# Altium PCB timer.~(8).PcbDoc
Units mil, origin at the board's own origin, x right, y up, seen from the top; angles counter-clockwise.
Board outline 1968.5 x 1968.5 mil, 2 copper layers (Top Layer, Bottom Layer); 56 components, 43 nets, 162 pads, 42 vias.
Unrouted connection lines stored in the file: 53.
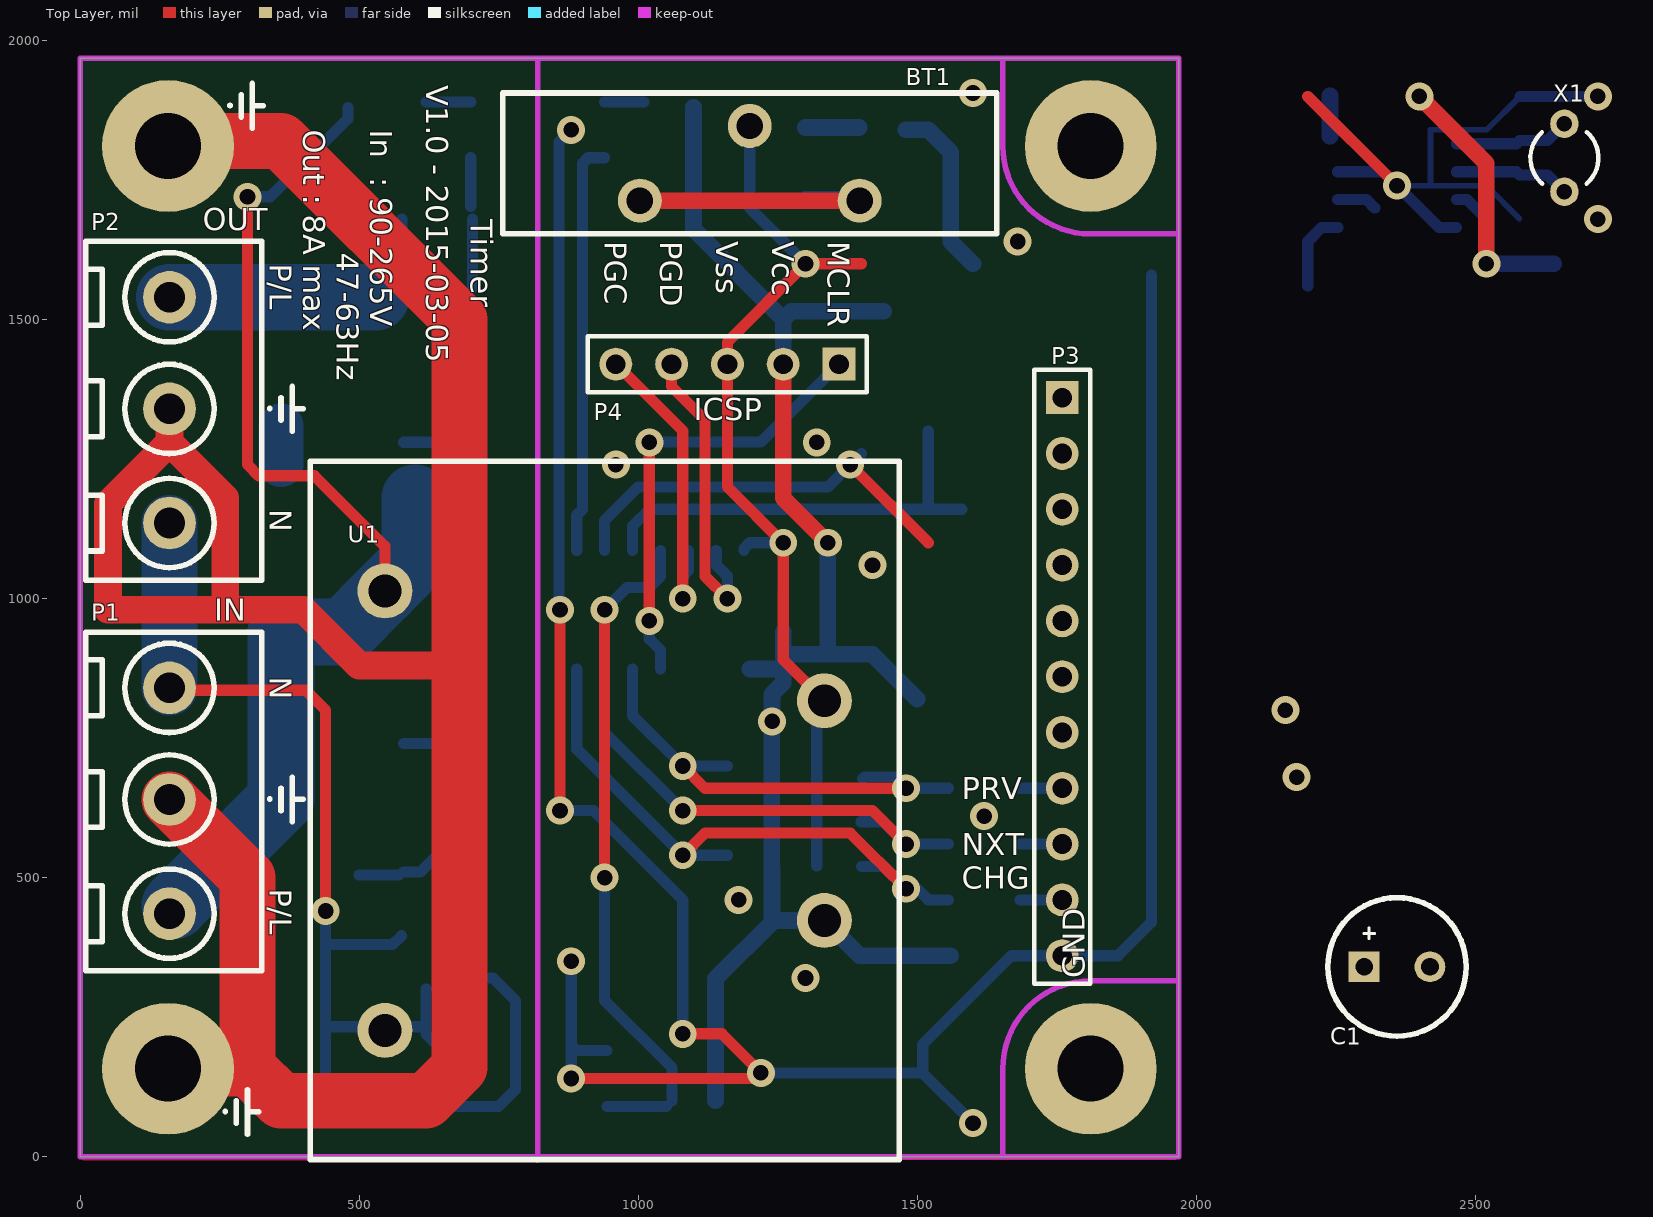
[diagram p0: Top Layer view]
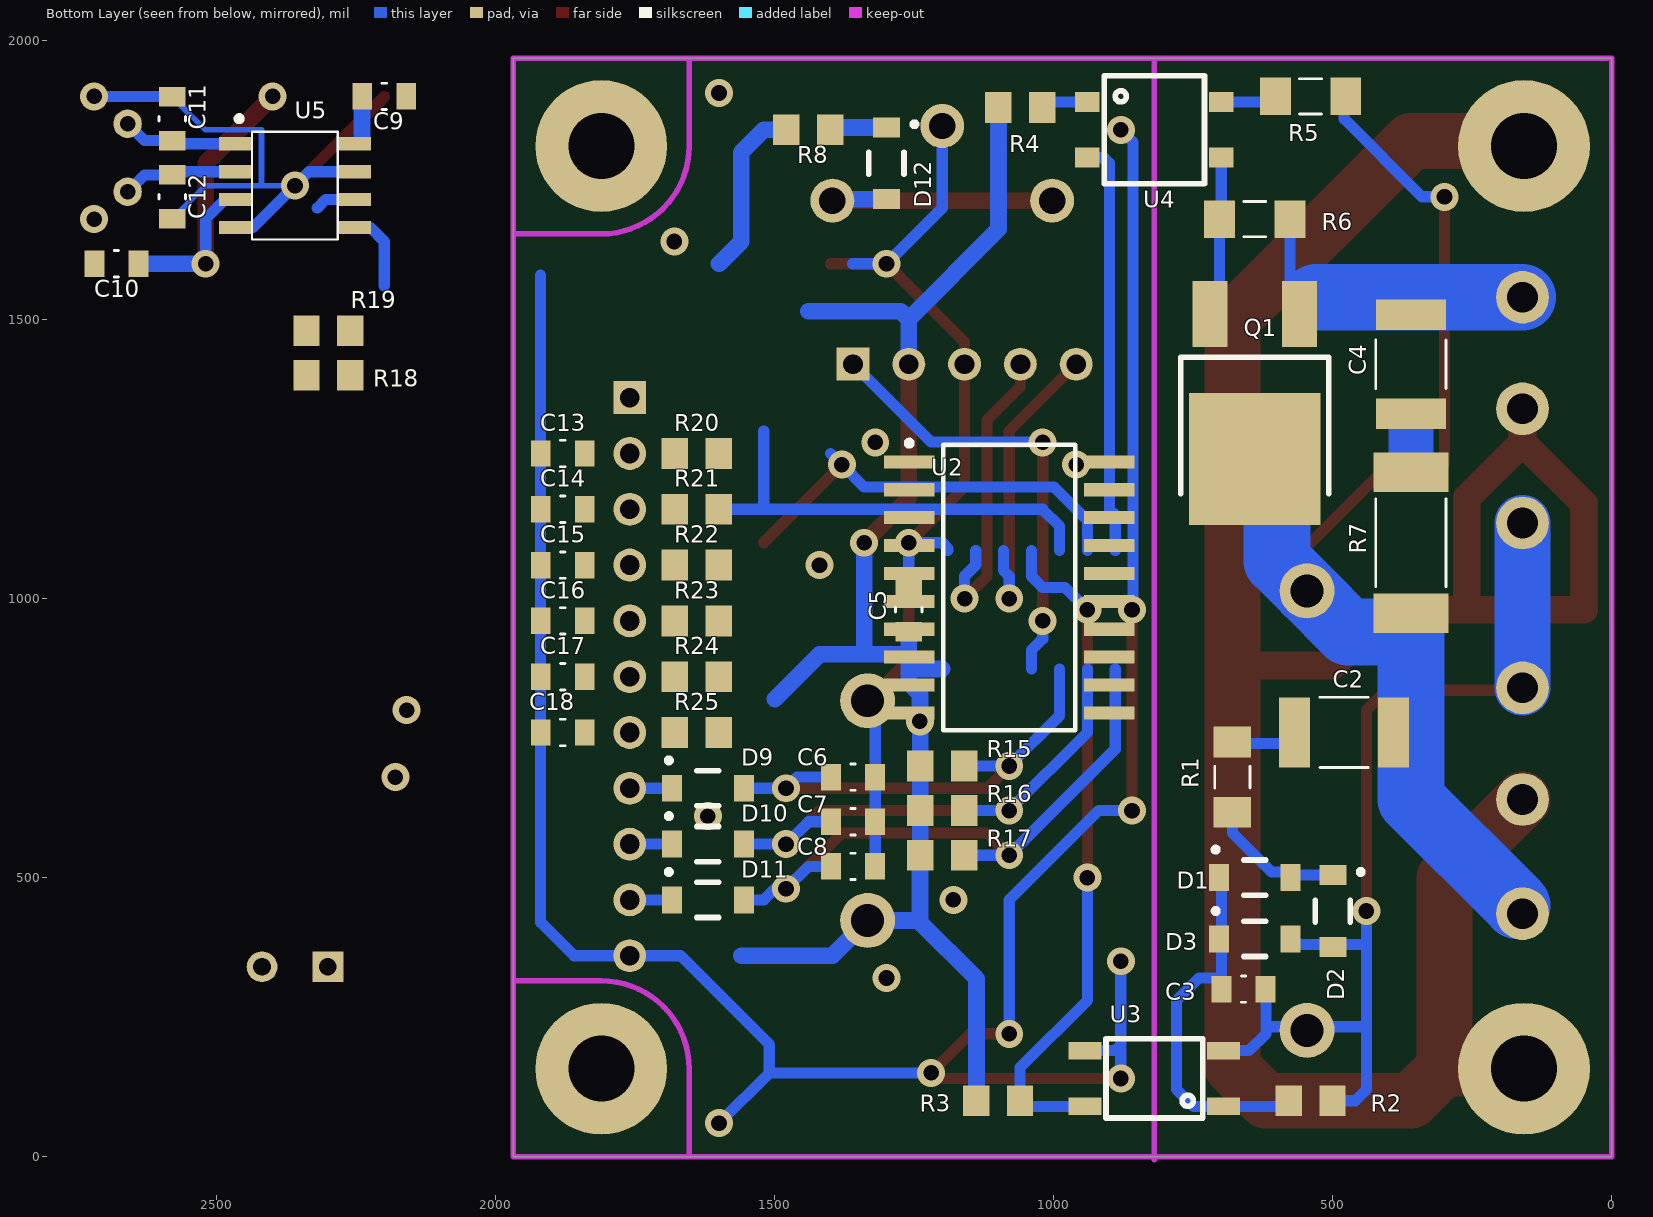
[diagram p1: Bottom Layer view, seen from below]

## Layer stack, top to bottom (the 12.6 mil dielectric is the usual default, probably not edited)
Top Layer: signal copper 1.4
Dielectric: core 12.6, FR-4, Dk 4.8
Bottom Layer: signal copper 1.4

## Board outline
0,0 1968.5,0 1968.5,1968.5 0,1968.5

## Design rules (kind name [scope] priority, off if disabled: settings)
Clearance RTC [InNetClass('RTC')] p1: gap=8
Clearance Earth [InNet('EARTH')] p2: gap=20
Clearance HT [InNetClass('HT') vs InNetClass('HT')] p3: gap=78.74
Clearance "plan masse" [All vs InNet('GND')] p4: gap=10
Clearance [All] p5: gap=20
HoleSize [All] p1: absolutevalues=TRUE maxlimit=196.85 minlimit=23.62 maxpercent=80.000 minpercent=20.000
PlaneConnect PlaneConnect_Via [isVia] p1: planeconnectstyle=Direct reliefexpansion=20 reliefentries=4 reliefconductorwidth=10 reliefairgap=10
PlaneConnect [All] p2: planeconnectstyle=Direct reliefexpansion=20 reliefentries=4 reliefconductorwidth=10 reliefairgap=10
PolygonConnect PolygonConnect_Via [IsVia] p1: connectstyle=Direct reliefconductorwidth=20 reliefentries=4 polygonreliefangle="90 Angle" airgapwidth=10
PolygonConnect [All] p2: connectstyle=Direct reliefconductorwidth=20 reliefentries=4 polygonreliefangle="90 Angle" airgapwidth=10
RoutingVias [All] p1: holewidth=39.37 width=78.74 viastyle="Through Hole" minholewidth=23.62 minwidth=31.5 maxholewidth=39.37 maxwidth=78.74
SilkToSolderMaskClearance SilkscreenOverComponentPads [IsPad] p1: minsilkscreentomaskgap=10 clearancetoexposedcopper=TRUE
SolderMaskExpansion [All] p1: expansion=4
Width overlay_width [(OnLayer('Top Overlay') OR OnLayer('Bottom Overlay'))] p1: maxlimit=10 minlimit=5 preferedwidth=10
Width [All] p2: maxlimit=150 minlimit=10 preferedwidth=20
25 further rules are at their usual default settings.

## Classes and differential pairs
net class RTC: NetC10_1 NetC11_1 NetC12_1
net class HT: N NetC4_1 NetC4_2 P

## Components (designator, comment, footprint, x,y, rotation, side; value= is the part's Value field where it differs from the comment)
BT1 "CR2032" BAT_2032 1200,1780 r0 top locked
C1 "470µ" CAP_6.3x2.5 2360,340 r0 top
C2 "10n 400V" C1812 480,760 r0 bottom
C3 "10n" C0805 660,300 r180 bottom
C4 "10n 400V" C1812 360,1420 r90 bottom
C5 "100n" C0805 1260,980 r270 bottom
C6 "100n" C0805 1360,680 r180 bottom
C7 "100n" C0805 1360,600 r180 bottom
C8 "100n" C0805 1360,520 r180 bottom
C9 "100n" C0805 2200,1900 r180 bottom
C10 "100p" C0805 2680,1600 r0 bottom
C11 "15p" C0805 2580,1860 r90 bottom
C12 "15p" C0805 2580,1720 r270 bottom
C13 "47p" C0805 1880,1260 r0 bottom
C14 "47p" C0805 1880,1160 r0 bottom
C15 "47p" C0805 1880,1060 r0 bottom
C16 "47p" C0805 1880,960 r0 bottom
C17 "47p" C0805 1880,860 r0 bottom
C18 "47p" C0805 1880,760 r0 bottom
D1 "MBR0520LT" SOD-123 640,500 r0 bottom
D2 "MBR0520LT" SOD-123 500,440 r90 bottom
D3 "5V1" SOD-123 640,390 r0 bottom
D9 "MBR0520LT" SOD-123 1620,660 r0 bottom
D10 "MBR0520LT" SOD-123 1620,560 r0 bottom
D11 "MBR0520LT" SOD-123 1620,460 r0 bottom
D12 "MBR0520LT" SOD-123 1300,1780 r90 bottom
P1 "5.08x3" "BORNIER 5.08X3" 160,640 r270 top locked
P2 "5.08x3" "BORNIER 5.08X3" 160,1340 r270 top locked
P3 "2.54x11" HDR1X11 1760,1360 r270 top
P4 "2.54x5" HDR1X5 1360,1420 r180 top locked
Q1 "BT137S-600D" DPAK 640,1310 r0 bottom
R1 "10k" R1206 680,680 r90 bottom
R2 "100k" R0805 540,100 r180 bottom
R3 "10k" R0805 1100,100 r0 bottom
R4 "1k" R0805 1060,1880 r0 bottom
R5 "56" R1206 540,1900 r0 bottom
R6 "330" R1206 640,1680 r0 bottom
R7 "100 1W" R2512 360,1100 r90 bottom
R8 "1k" R0805 1440,1840 r0 bottom
R15 "10k" R0805 1200,700 r0 bottom
R16 "10k" R0805 1200,620 r0 bottom
R17 "10k" R0805 1200,540 r0 bottom
R18 "2k2" R0805 2300,1400 r180 bottom
R19 "2k2" R0805 2300,1480 r0 bottom
R20 "1k" R0805 1640,1260 r0 bottom
R21 "1k" R0805 1640,1160 r0 bottom
R22 "1k" R0805 1640,1060 r0 bottom
R23 "1k" R0805 1640,960 r0 bottom
R24 "1k" R0805 1640,860 r0 bottom
R25 "1k" R0805 1640,760 r0 bottom
U1 "AC-DC 5V 600mA" "AC-DC 3W" 940,620 r0 top locked
U2 "PIC16F1825" SOIC-20 1080,1020 r180 bottom
U3 "PC357N14J00F" OPTO_PC357N14J00F 820,140 r0 bottom
U4 "VOM160RT" OPTO_VOM160RT 820,1840 r180 bottom
U5 "MCP7940N" SOIC-8 2360,1740 r180 bottom
X1 "32.768kHz" R38 2660,1790 r0 top

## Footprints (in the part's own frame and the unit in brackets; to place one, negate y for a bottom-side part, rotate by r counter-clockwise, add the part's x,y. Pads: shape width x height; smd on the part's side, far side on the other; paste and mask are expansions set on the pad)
"AC-DC 3W" [mm]
  round 2.5 hole 1.5: 1(-10,10) 2(-10,-10) 3(10,-5) 4(10,5)
  silkscreen extent -13.4,-15.9 13.4,15.9, body extent -13.4,-15.9 13.4,15.9, height 19.5
BAT_2032 [mm] "Battery holder 2032"
  round 2 hole 1.2: +(-5,-1.7) +(5,-1.7) -(0,1.7)
  silkscreen extent -11.25,-3.2 11.25,3.2, body extent -11.25,-3.2 11.25,3.2, height 25
"BORNIER 5.08X3" [mm] "Bornier 5.08x3"
  round 2.4 hole 1.4: 1(-5.08,0) 2(0,0) 3(5.2,0)
  silkscreen extent -7.62,-3.8 7.8,4.2
C0805 [mm]
  rect 0.9x1.2 smd: 1(-1,0) 2(1,0)
  silkscreen extent -0.1,-0.6 0.1,0.6, body extent -1,-0.6 1,0.6, height 1.2
C1812 [mm]
  rect 1.4x3.2 smd: 1(-2.25,0) 2(2.25,0)
  silkscreen extent -1.1,-1.6 1.1,1.6, body extent -2.25,-1.6 2.25,1.6, height 3.2
CAP_6.3x2.5 [mm] "Capacitor throug hole dia=6.3mm, H=11mm, spacing=2.5mm"
  rect 1.4x1.4 hole 0.8: 1(-1.5,0)
  round 1.4 hole 0.8: 2(1.5,0)
  silkscreen extent -3.15,-3.15 3.15,3.15, body extent -3.12,-3.14 3.15,3.14, height 11
DPAK [mm] "DPAK"
  rect 1.6x3 smd: 1(-2.032,-5.08) 3(2.032,-5.08)
  rect 6x6 smd: 2(0,1.524)
  silkscreen extent -3.36,-3.11 3.36,3.11, body extent -3.36,-3.11 3.36,3.11, height 2.38
HDR1X5 [mm] "Connector; Header; 5 Position"
  rect 1.5x1.5 hole 0.9: 1(0,0)
  round 1.5 hole 0.9: 2(2.54,0) 3(5.08,0) 4(7.62,0) 5(10.16,0)
  silkscreen extent -1.27,-1.27 11.43,1.27
HDR1X11 [mm] "Connector; Header; 11 Position"
  rect 1.5x1.5 hole 0.9: 1(0,0)
  round 1.5 hole 0.9: 2(2.54,0) 3(5.08,0) 4(7.62,0) 5(10.16,0) 6(12.7,0) 7(15.24,0) 8(17.78,0) 9(20.32,0) 10(22.86,0) 11(25.4,0)
  silkscreen extent -1.27,-1.27 26.67,1.27
OPTO_PC357N14J00F [mm] "optocoupleur"
  rect 1.5x0.8 smd: 1(-3.15,1.27) 2(-3.15,-1.27) 3(3.15,-1.27) 4(3.15,1.27)
  silkscreen extent -2.2,-1.8 2.2,1.8, body extent -2.2,-1.8 2.2,1.8, height 2.6
OPTO_VOM160RT [mm] "Opto-triac"
  rect 1.11x0.91 smd: 1(-3.048,1.27) 2(-3.048,-1.27) 3(3.048,-1.27) 4(3.048,1.27)
  silkscreen extent -2.28,-2.46 2.28,2.46, body extent -2.28,-2.46 2.28,2.46, height 1.97
R38 [mm] "Crystal, Thru-Hole; 2 Leads; Body 3.1 x 8.2 mm (Dia.xH)"
  round 1.3 hole 0.7: 1(0,1.55) 2(0,-1.55)
  silkscreen extent -1.55,-1.19 1.55,1.17
R0805 [mm] "0.125W"
  rect 1.2x1.4 smd: 1(-1,0) 2(1,0)
  body extent -1,-0.63 1,0.63, height 1.2
R1206 [mm] "0.25W"
  rect 1.4x1.7 smd: 1(-1.6,0) 2(1.6,0)
  silkscreen extent -0.5,-0.8 0.5,0.8, body extent -1.6,-0.8 1.6,0.8, height 1.6
R2512 [mm] "1W"
  rect 1.8x3.4 smd: 1(-3.2,0) 2(3.2,0)
  silkscreen extent -2,-1.6 2,1.6, body extent -3.2,-1.6 3.2,1.6, height 5
SOD-123 [mm] "Diode"
  rect 0.91x1.22 smd: 1(-1.635,0) 2(1.635,0)
  silkscreen extent -0.5,-1.37 1.88,0.8, body extent -1.35,-0.8 1.35,0.8, height 1.17
SOIC-8 [mm] "8-Pin Plastic Narrow Body Small Outline Integrated Circuit 1.27 mm Pitch, IPC Medium Density"
  rect 1.5x0.6 smd: 1(-2.7,1.905) 2(-2.7,0.635) 3(-2.7,-0.635) 4(-2.7,-1.905) 5(2.7,-1.905) 6(2.7,-0.635) 7(2.7,0.635) 8(2.7,1.905)
  silkscreen extent -2.67,-2.45 1.95,3.17, body extent -1.95,-2.45 1.95,2.45, height 1.76
SOIC-20 [mm] "20-Pin Plastic Wide Body Small Outline Integrated Circuit 1.27 mm Pitch, IPC Medium Density"
  rect 2.3x0.6 smd: 1(-4.55,5.715) 2(-4.55,4.445) 3(-4.55,3.175) 4(-4.55,1.905) 5(-4.55,0.635) 6(-4.55,-0.635) 7(-4.55,-1.905) 8(-4.55,-3.175) 9(-4.55,-4.445) 10(-4.55,-5.715) 11(4.55,-5.715) 12(4.55,-4.445) 13(4.55,-3.175) 14(4.55,-1.905) 15(4.55,-0.635) 16(4.55,0.635) 17(4.55,1.905) 18(4.55,3.175) 19(4.55,4.445) 20(4.55,5.715)
  silkscreen extent -4.67,-6.5 3,6.69, body extent -3.75,-6.4 3.75,6.4, height 2.65

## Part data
BT1: library part Battery, "Multicell Battery"
C1: library part "Cap Pol1", "Polarized Capacitor (Radial)"
C2 C3 C4 C5 C6 C7 C8 C9 C10 C11 C12 C13 C14 C15 C16 C17 C18: library part Cap, "Capacitor"
D1 D2 D9 D10 D11 D12: library part "Diode 1N4001", "1 Amp General Purpose Rectifier"
D3: library part "D Zener", "Zener Diode"
P1 P2: library part "Header 3", "Header, 3-Pin"
P3: library part "Header 11", "Header, 11-Pin"
P4: library part "Header 5", "Header, 5-Pin"
Q1: library part Triac, "Silicon Bidirectional Triode Thyristor"
R1 R2 R3 R4 R5 R6 R7 R8 R15 R16 R17 R18 R19 R20 R21 R22 R23 R24 R25: library part Res2, "Resistor"
U1: library part AC-DC
U2: library part PIC16F1829
U3: library part Optoisolator1, "4-Pin Phototransistor Optocoupler"
U4: library part "Opto TRIAC", "Opto-Triac"
U5: library part "RTC- MCP7940N"
X1: library part XTAL, "Crystal Oscillator"

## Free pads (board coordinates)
  round 236.22 hole 118.11: 0(157.48,157.48) 0(157.48,1811.02) 0(1811.02,157.48) 0(1811.02,1811.02)

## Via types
v1: diameter 50, hole 28, Top Layer to Bottom Layer, 42 vias

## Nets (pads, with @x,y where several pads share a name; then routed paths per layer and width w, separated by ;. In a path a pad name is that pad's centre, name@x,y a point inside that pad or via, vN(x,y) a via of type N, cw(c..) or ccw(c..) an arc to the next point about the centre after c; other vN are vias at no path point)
BP_CHG: C8.1 D11.1 R17.1 U2.12 | length 1187.4
  Top Layer w20: v1(1080,540) 1120,580 1380,580 v1(1480,480) 1440,520
  Bottom Layer w20: 890,873.7 890,730 v1(1080,540) R17.1@1160,540 ; C8.1@1400,520 1440,520 v1(1480,480) 1500,480 1520,460 D11.1
BP_NXT: C7.1 D10.1 R16.1 U2.2 | length 989.4
  Top Layer w20: v1(1080,620) 1420,620 v1(1480,560)
  Bottom Layer w20: 940,873.7 940,760 v1(1080,620) R16.1@1160,620 ; C7.1 1440,600 v1(1480,560) D10.1
BP_PRV: C6.1 D9.1 R15.1 U2.3 | length 870.3
  Top Layer w20: v1(1080,700) 1120,660 v1(1480,660)
  Bottom Layer w20: 990,873.7 990,790 v1(1080,700) R15.1@1160,700 ; C6.1@1402.38,676.99 1405.39,680 1460,680 v1(1480,660) D9.1
EARTH: P1.2 P2.2 pad.0@157.48,157.48 pad.0@157.48,1811.02 | length 4671.4
  Top Layer w50: P2.2 160,1280 ; 680,880 500,880 400,980 260,980 ; 160,1280 50,1170 50,980 260,980 ; 160,1280 260,1180 260,980
  Top Layer w100: pad.0@157.48,1811.02 166.46,1820 360,1820 680,1500 680,880 680,160 620,100 360,100 302.52,157.48 157.48,157.48 300,157.48 300,500 P1.2
GND: BT1.- C1.2 C5.1 C6.2 C7.2 C8.2 C9.2 C10.2 C11.2 C12.2 C13.2 C14.2 C15.2 C16.2 C17.2 C18.2 P3.11 P4.3 U1.4 U2.20 U3.3 U5.4 U5.7 | length 7654.4
  Top Layer w20: v1(860,620) v1(860,980) ; v1(880,140) v1@1210,140 ; v1(1080,220) 1150,220 v1(1220,150) ; U1.4 1260,890.55 v1(1260,1100) 1160,1200 P4.3 1160,1460 v1(1300,1600) 1400,1600 ; 2200,1900 v1(2360,1740)
  Bottom Layer w10: v1(2360,1740) 2420,1740 ; C12.2@2579.37,1680.63 2520,1740 2420,1740 ; C11.2 2520.63,1840 2420,1840 2420,1740
  Bottom Layer w20: v1(860,620) 920,620 1080,460 1080,230 v1@1070,220 ; v1(860,980) 858.19,981.81 858.19,1818.19 v1(880,1840) ; v1(880,140) 880,200 ; v1(880,350) 880,200 ; U3.3 890,190 880,200 ; 1190,1086.3 1190,1090 1200,1100 v1(1260,1100) C5.1 ; BT1.- 1200,1700 v1(1300,1600) 1360.63,1600 ; v1(1220,150) 1510,150 ; C8.2@1320,520.63 U1.4@1320,840 ; v1(1600,60) 1510,150 ; 1920,1580 1920,420 1860,360 1669.06,360 1510,200.94 1510,150 ; U5.7 2335,1765 v1(2360,1740) 2435,1665 U5.4 ; C11.2@2580.63,1900 v1(2720,1900)
  other v1: 1300,320 1180,460 1620,610 2180,680 2160,800 1420,1060 960,1240 1320,1280 1680,1640 2720,1680 1600,1905.98
LCD_D4: R22.1 U2.7
LCD_D5: R23.1 U2.8
LCD_D6: R24.1 U2.9
LCD_D7: R25.1 U2.10
LCD_E: R21.1 U2.6
LCD_RS: R20.1 U2.5
MCLR: P4.1 U2.4 | length 812.4
  Top Layer w20: v1(1020,960) v1(1020,1280)
  Bottom Layer w20: v1(1020,960) 1020,927.47 1040,907.47 1040,873.7 ; v1@1020,1280.39 1220.39,1280.39 P4.1
N: C3.2 D2.1 D3.1 P1.1 P2.3 R2.2 U1.2 U3.2 | length 1834.8
  Top Layer w20: P1.1@164.25,835.75 404.25,835.75 440,800 v1(440,440)
  Bottom Layer w20: 440,380 560,380 D3.1@575.63,395.63 ; v1(440,440) 440,232.6 ; R2.2 460,100 440,120 440,232.6 ; 620,232.6 540,232.6 440,232.6 ; C3.2 620,300 620,220 650,190 U3.2
  Bottom Layer w50: U1.2@540,232.6 U1.2
  Bottom Layer w100: P1.1 P2.3
NetBT1_1: BT1.+ D12.1 | length 488
  Top Layer w30: BT1.+@1003.15,1713.07 BT1.+@1396.85,1713.07
  Bottom Layer w30: D12.1 BT1.+@1394.29,1715.63
NetC2_2: C2.2 R1.2 | length 100
  Bottom Layer w20: C2.2@580,740 R1.2@680,740
NetC3_1: C3.1 D1.2 D3.2 R2.1 U3.1 | length 639.6
  Bottom Layer w20: R2.1@580,90 U3.1 750,90 780,120 780,280 740,320 699.37,320 D1.2@699.37,490
NetC4_1: C4.1 R7.2 | length 70
  Bottom Layer w80: R7.2@360,1240 C4.1@360,1310
NetC4_2: C4.2 P2.1 Q1.1 R6.1 | length 523
  Bottom Layer w20: Q1.1@577.01,1527.01 R6.1
  Bottom Layer w120: P2.1 Q1.1@530,1540
NetC10_1: C10.1 R8.2 U5.3 | length 932.3
  Top Layer w30: v1(2400,1900) 2520,1780 v1(2520,1600)
  Bottom Layer w20: U5.3 2485,1715 2520,1680 v1(2520,1600)
  Bottom Layer w30: R8.2 1520,1840 1560,1800 1560,1640 1600,1600 ; v1(2520,1600) C10.1
NetC11_1: C11.1 U5.1 X1.1 | length 200.7
  Bottom Layer w20: U5.1 C11.1@2574.37,1815 ; C11.1 2629.61,1820.63 X1.1
NetC12_1: C12.1 U5.2 X1.2 | length 200.7
  Bottom Layer w20: U5.2 C12.1@2574.37,1765 ; C12.1 2629.61,1759.37 X1.2
NetD1_1: D1.1 D2.2 R1.1 | length 220.3
  Bottom Layer w20: D2.2 D1.1@571.26,504.37 ; D1.1@580,510 610,510 680,580 R1.1@680,600
NetD12_2: D12.2 R8.1 | length 96.3
  Bottom Layer w30: D12.2 R8.1@1396.26,1844.37
NetQ1_3: Q1.3 R6.2 U4.3 | length 210
  Bottom Layer w20: R6.2@700,1702.99 U4.3 ; Q1.3@702.99,1557.01 R6.2
NetR4_1: R4.1 U4.1 | length 70
  Bottom Layer w20: U4.1 R4.1@1010,1890
NetR5_2: R5.2 U4.4 | length 80
  Bottom Layer w20: R5.2@620,1890 U4.4
P: C2.1 P1.3 Q1.2 R5.1 R7.1 U1.1 | length 2179
  Top Layer w20: v1(300,1720) 300,1240 320,1220 420,1220 546.3,1093.7 U1.1
  Bottom Layer w20: v1(300,1720) 340,1720 480,1860 R5.1@480,1880 ; Q1.2@580,1280 Q1.2@660,1280
  Bottom Layer w120: P1.3@170,450 360,640 360,940 472.6,940 U1.1 600,1067.4 Q1.2@600,1180
P_BP_CHG: D11.2 P3.10 | length 75.6
  Bottom Layer w20: D11.2 P3.10
P_BP_NXT: D10.2 P3.9 | length 75.6
  Bottom Layer w20: D10.2 P3.9
P_BP_PRV: D9.2 P3.8 | length 75.6
  Bottom Layer w20: D9.2 P3.8
P_LCD_D4: C15.1 P3.4 R22.2
P_LCD_D5: C16.1 P3.5 R23.2
P_LCD_D6: C17.1 P3.6 R24.2
P_LCD_D7: C18.1 P3.7 R25.2
P_LCD_E: C14.1 P3.3 R21.2
P_LCD_RS: C13.1 P3.2 R20.2
PGC: P4.5 U2.18 | length 560.1
  Top Layer w20: P4.5 1080,1300 v1(1080,1000)
  Bottom Layer w20: v1(1080,1000) 1080,1040 1090,1050 1090,1086.3
PGD: P4.4 U2.19 | length 556
  Top Layer w20: P4.4 1060,1380 1120,1320 1120,1040 v1(1160,1000)
  Bottom Layer w20: 1140,1086.3 1140,1060 1160,1040 v1(1160,1000)
POWER: U2.14 U4.2 | length 742
  Bottom Layer w20: 890,1086.3 890,1150 900,1160 900,1780 910,1790 U4.2
SCL: R18.2 U2.11 U5.6 | length 858.6
  Bottom Layer w20: 990,1086.3 990,1130 1020,1160 1520,1160 ; 1520,1300 1520,1160 ; 1580,1160 1520,1160 ; U5.6 2305,1715 2320,1700
SDA: R19.2 U2.13 U5.5 | length 905.5
  Top Layer w20: v1(1380,1240) 1520,1100
  Bottom Layer w20: 940,1086.3 940,1140 1000,1200 1340,1200 v1(1380,1240) 1400,1260 ; 2200,1560 2200,1640 2225,1665 U5.5
SIGNAL: R3.1 U2.17 U3.4 | length 1207.7
  Top Layer w20: v1(940,500) v1(940,980)
  Bottom Layer w20: v1(940,500) 940,280 1060.63,159.37 R3.1 ; v1(940,980) 980,1020 1020,1020 1040,1040 1040,1086.3 ; U3.4 R3.1@1050.63,90
VCC: C1.1 C5.2 C9.1 P3.1 P4.2 R3.2 R4.2 R15.2 R16.2 R17.2 R18.1 R19.1 U1.3 U2.1 U5.8 | length 2894
  Top Layer w30: P4.2 1260,1180 v1(1340,1100)
  Bottom Layer w30: R4.2 1099.37,1661.89 1260,1501.26 1260,1500 ; R3.2@1138.74,100 1138.74,318.74 1243.15,423.15 U1.3 ; 1200,873.7 1253.7,873.7 ; v1@1239.37,780 R15.2 R16.2 1240,423.15 ; v1(1240,780) 1240,828.61 1260,848.61 1260,900 ; C5.2 1260,900 ; P4.2 1260,1500 ; U1.3@1337.8,419.06 1396.85,360 1560,360 ; v1(1340,1100) 1340,900 ; 1440,1515 1275,1515 1260,1500 ; 1500,820 1420,900 1340,900 ; 2240,1828.7 C9.1@2240,1900.63 ; 1260,900 1340,900
pads on no net: U2.15 U2.16

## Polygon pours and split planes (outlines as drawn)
EARTH on Top Layer "Earth-Top" (solid, shelved, pour order 3): 0,0 5.98,-5.98 820,-5.98 820,1968.5 0,1968.5
GND on Top Layer "GND-Top" (solid, remove dead copper, shelved, pour order 7): 1968.5,0 1962.52,-5.98 820,-5.98 820,1968.5 1968.5,1968.5
GND on Bottom Layer "GND-Bottom" (solid, remove dead copper, shelved, pour order 5): 1968.5,0 820,0 820,1968.5 1968.5,1968.5

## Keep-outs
Top Layer:
  lines w10: 820,-5.98 820,1968.5 ; 1653.54,0 1653.54,157.48 cw(c1811.02,157.48) 1811.02,314.96 1968.5,314.96 ; 1653.54,1968.5 1653.54,1811.02 ccw(c1811.02,1811.02) 1811.02,1653.54 1968.5,1653.54
Bottom Layer:
  lines w10: 820,-5.98 820,1968.5 ; 1653.54,0 1653.54,157.48 cw(c1811.02,157.48) 1811.02,314.96 1968.5,314.96 ; 1653.54,1968.5 1653.54,1811.02 ccw(c1811.02,1811.02) 1811.02,1653.54 1968.5,1653.54
Keep-Out Layer:
  the board outline again, w10

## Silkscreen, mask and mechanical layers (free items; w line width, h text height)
Top Overlay:
  lines w10: 260,80 260,81 ; 268.5,1882.99 268.5,1883.99 ; 280,60 280,100 ; 288.5,1862.99 288.5,1902.99 ; 300,40 300,120 ; 300,80 320,80 ; 308.5,1842.99 308.5,1922.99 ; 308.5,1882.99 328.5,1882.99 ; 340,640 340,641 ; 340,1340 340,1341 ; 360,620 360,660 ; 360,1320 360,1360 ; 380,600 380,680 ; 380,640 400,640 ; 380,1300 380,1380 ; 380,1340 400,1340
  text "V1.0 - 2015-03-05" at 620,1920 h40 r270
  text "Out : 8A max" at 400,1840 h40 r270
  text "In  : 90-265V" at 520,1840 h40 r270
  text "Timer" at 700,1680 h40 r270
  text "OUT" at 220,1660 h40
  text "PGC" at 940,1640 h40 r270
  text "PGD" at 1040,1640 h40 r270
  text "Vss" at 1140,1640 h40 r270
  text "Vcc" at 1240,1640 h40 r270
  text "MCLR" at 1340,1640 h40 r270
  text "47-63Hz" at 460,1620 h40 r270
  text "P/L" at 340,1600 h40 r270
  text "5V" at 3100,1580 h40
  text "SCL" at 3060,1500 h40
  text "SDA" at 3080,1420 h40
  text "http://aerith.fr" at 3080,1340 h40 r270
  text "ICSP" at 1100,1320 h40
  text "By : aeris" at 3280,1220 h40 r270
  text "N" at 340,1160 h40 r270
  text "IN" at 240,960 h40
  text "N" at 340,860 h40 r270
  text "PRV" at 1580,640 h40
  text "NXT" at 1580,540 h40
  text "P/L" at 340,480 h40 r270
  text "CHG" at 1580,480 h40
  text "GND" at 1800,320 h40 r90

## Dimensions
0,0 to 0,1968.5 on Drill Guide
1968.5,1968.5 to 0,1968.5 on Drill Guide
